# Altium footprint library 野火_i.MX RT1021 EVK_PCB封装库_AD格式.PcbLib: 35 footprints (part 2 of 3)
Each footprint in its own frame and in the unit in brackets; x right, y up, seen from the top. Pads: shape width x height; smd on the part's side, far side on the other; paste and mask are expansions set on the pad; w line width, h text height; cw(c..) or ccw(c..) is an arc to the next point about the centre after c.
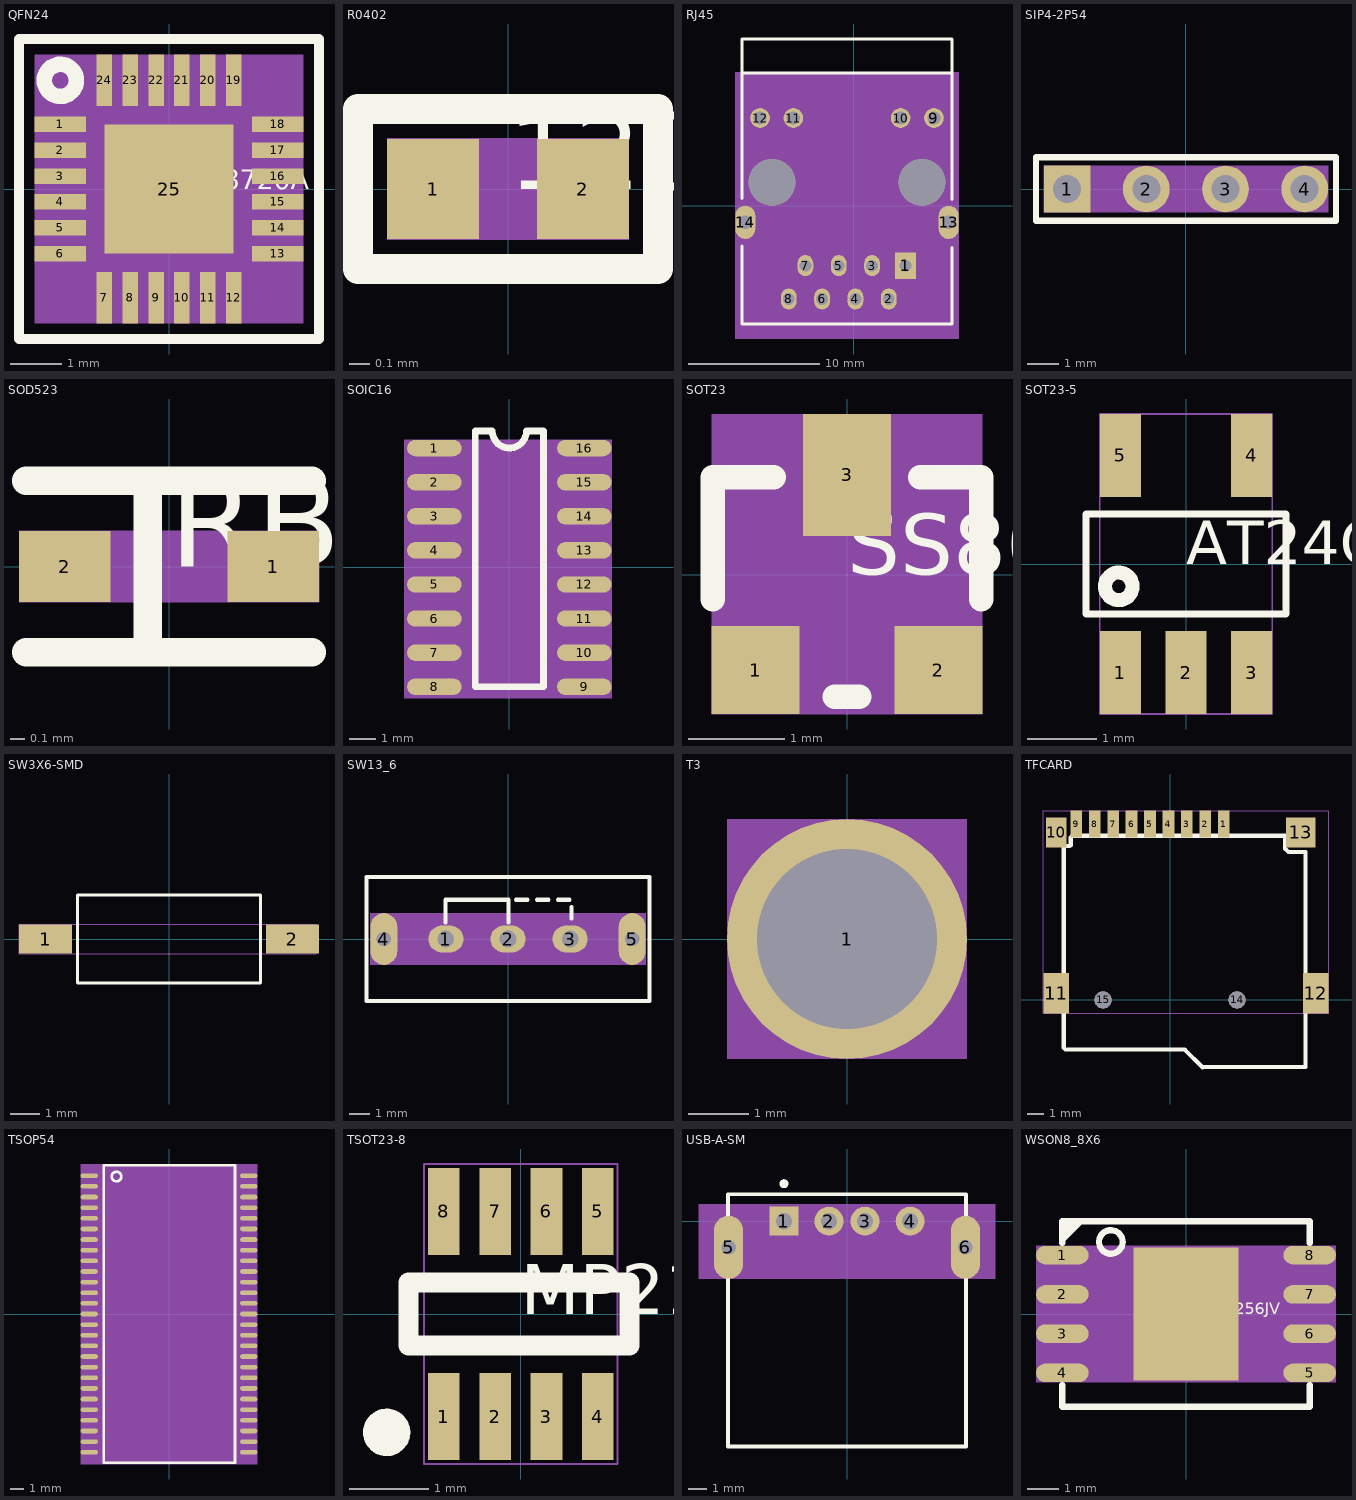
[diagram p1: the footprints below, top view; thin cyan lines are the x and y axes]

## QFN24 [mm] "QFN24"
pads (25):
  rect 1x0.3 smd: 1(-2.1,1.25) 2(-2.1,0.75) 3(-2.1,0.25) 4(-2.1,-0.25) 5(-2.1,-0.75) 6(-2.1,-1.25) 13(2.1,-1.25) 14(2.1,-0.75) 15(2.1,-0.25) 16(2.1,0.25) 17(2.1,0.75) 18(2.1,1.25)
  rect 0.3x1 smd: 7(-1.25,-2.1) 8(-0.75,-2.1) 9(-0.25,-2.1) 10(0.25,-2.1) 11(0.75,-2.1) 12(1.25,-2.1) 19(1.25,2.1) 20(0.75,2.1) 21(0.25,2.1) 22(-0.25,2.1) 23(-0.75,2.1) 24(-1.25,2.1)
  rect 2.5x2.5 smd: 25(0,0)
Top Overlay:
  circle w0.3: c-2.1,2.1 r0.31
  lines w0.2: -2.9,-2.9 -2.9,2.9 2.9,2.9 2.9,-2.9 -2.9,-2.9
  text "LAN8720A" at 0,0 h0.38
Mechanical 6:
  text "4" at -2.1,-0.098 h0.38
  text "19" at 1.25,2.405 h0.38
  text "1" at -2.1,1.402 h0.38
  text "14" at 2.1,-0.445 h0.38
  text "6" at -2.1,-1.098 h0.38
  text "24" at -1.25,2.405 h0.38
  text "15" at 2.1,0.055 h0.38
  text "25" at 0,0.305 h0.38
  text "21" at 0.25,2.405 h0.38
  text "20" at 0.75,2.405 h0.38
  text "2" at -2.1,0.902 h0.38
  text "23" at -0.75,2.405 h0.38
  text "22" at -0.25,2.405 h0.38
  text "3" at -2.1,0.402 h0.38
  text "5" at -2.1,-0.598 h0.38
  text "16" at 2.1,0.555 h0.38
  text "18" at 2.1,1.555 h0.38
  text "17" at 2.1,1.055 h0.38
  text "10" at 0.25,-1.795 h0.38
  text "7" at -1.25,-1.948 h0.38
  text "8" at -0.75,-1.948 h0.38
  text "12" at 1.25,-1.795 h0.38
  text "13" at 2.1,-0.945 h0.38
  text "11" at 0.75,-1.795 h0.38
  text "9" at -0.25,-1.948 h0.38
Mechanical 7:
  region: -2.6,-2.6 2.6,-2.6 2.6,2.6 -2.6,2.6
Mechanical 8:
  lines w0.2: -2.05,-2.05 -2.05,2.05 2.05,2.05 2.05,-2.05 -2.05,-2.05
3D body: height 3.81, standoff 0, extent -2.6,-2.6 2.6,2.6

## R0402 [mm] "R0402"
pads (2):
  rect 0.46x0.5 smd: 1(-0.375,0) 2(0.375,0)
Top Overlay:
  lines w0.15: -0.75,-0.4 -0.75,0.4 0.75,0.4 0.75,-0.4 -0.75,-0.4
  text "120 Ohm" at 0,0 h0.38
Mechanical 6:
  text "2" at 0.375,0.152 h0.38
  text "1" at -0.375,0.152 h0.38
Mechanical 7:
  region: -0.605,-0.255 0.605,-0.255 0.605,0.255 -0.605,0.255
3D body: height 3.81, standoff 0, extent -0.605,-0.255 0.605,0.255

## RJ45 [mil] "RJ45"
pads (16):
  rect 62.99x78.74 / inner round 60 / far side rect 62.99x78.74 hole 35.43: 1(155.2,-180)
  oval 47.24x62.99 / inner round 60 / far side oval 47.24x62.99 hole 35.43: 2(105.2,-280) 3(55.2,-180) 4(5.2,-280) 5(-44.8,-180) 6(-94.8,-280) 7(-144.8,-180) 8(-194.8,-280)
  round 59.06 / inner round 60 / far side round 59.06 hole 40.16: 9(240.83,262.91) 10(140.83,262.91) 11(-180.83,262.91) 12(-280.83,262.91)
  oval 60x100 / inner round 60 / far side oval 60x100 hole 40: 13(285.12,-50.08) 14(-325.12,-50.08)
  round 140 / inner round 60 / far side round 140 hole 140: " "(-245,70) " "(205,70)
Top Overlay:
  lines w7.87: -334.96,397.76 294.96,397.76
  lines w10: -334.96,-120.83 -334.96,-355 294.96,-355 294.96,-125.98 ; -334.96,22.64 -334.96,499.92 294.96,499.92 294.96,18.94
Mechanical 6:
  text "14" at -345.12,-50.08 h25
  text "13" at 265.12,-50.08 h25
  text "11" at -200.83,262.91 h25
  text "10" at 120.83,262.91 h25
  text "7" at -154.8,-180 h25
  text "8" at -204.8,-280 h25
  text "1" at 145.2,-180 h25
  text "2" at 95.2,-280 h25
  text "3" at 45.2,-180 h25
  text "6" at -104.8,-280 h25
  text "12" at -300.83,262.91 h25
  text "9" at 230.83,262.91 h25
  text "5" at -54.8,-180 h25
  text "4" at -4.8,-280 h25
Mechanical 7:
  region: -355.12,-400 315.12,-400 315.12,400 -355.12,400
3D body: height 150, standoff 0, extent -355.12,-400 315.12,400

## SIP4-2P54 [mil] "SIP4-2P54"
pads (4):
  rect 59.06x59.06 / inner round 60 / far side rect 59.06x59.06 hole 35.43: 1(-150,0)
  round 59.06 / inner round 60 / far side round 59.06 hole 35.43: 2(-50,0) 3(50,0) 4(150,0)
Top Overlay:
  lines w7.87: -189.37,-40 -189.37,40 189.57,40 189.57,-40 -189.37,-40
Mechanical 6:
  text "2" at -40,0 h25
  text "3" at 60,0 h25
  text "4" at 160,0 h25
  text "1" at -140,0 h25
Mechanical 7:
  region: -179.53,-29.53 179.53,-29.53 179.53,29.53 -179.53,29.53
3D body: height 150, standoff 0, extent -179.53,-29.53 179.53,29.53

## SOD523 [mm] "SOD523"
pads (2):
  rect 0.64x0.5 smd: 1(0.73,0) 2(-0.73,0)
Top Overlay:
  lines w0.2: -1,-0.6 1,-0.6 ; -1,0.6 1,0.6 ; -0.15,-0.575 -0.15,0.6
  text "RB521S30" at 0,0 h0.64
Mechanical 6:
  text "2" at -0.73,-0.254 h0.64
  text "1" at 0.73,-0.254 h0.64
Mechanical 7:
  region: -1.05,-0.25 1.05,-0.25 1.05,0.25 -1.05,0.25
3D body: height 3.81, standoff 0, extent -1.05,-0.25 1.05,0.25

## SOIC16 [mil] "SOIC16"
pads (16):
  oval 80x24 smd: 1(-110,175) 2(-110,125) 3(-110,75) 4(-110,25) 5(-110,-25) 6(-110,-75) 7(-110,-125) 8(-110,-175) 9(110,-175) 10(110,-125) 11(110,-75) 12(110,-25) 13(110,25) 14(110,75) 15(110,125) 16(110,175)
Top Overlay:
  lines w10: -50,-175 -50,200 -25,200 ccw(c0,200) 25,200 50,200 50,-175 -50,-175
Mechanical 6:
  text "3" at -110,65 h25
  text "16" at 110,155 h25
  text "7" at -110,-135 h25
  text "8" at -110,-185 h25
  text "4" at -110,15 h25
  text "2" at -110,115 h25
  text "5" at -110,-35 h25
  text "6" at -110,-85 h25
  text "1" at -110,165 h25
  text "14" at 110,55 h25
  text "11" at 110,-95 h25
  text "15" at 110,105 h25
  text "13" at 110,5 h25
  text "10" at 110,-145 h25
  text "12" at 110,-45 h25
  text "9" at 110,-185 h25
Mechanical 7:
  region: -154,-192 150,-192 150,187 -154,187
3D body: height 150, standoff 0, extent -154,-192 150,187

## SOT23 [mil] "SOT23"
pads (3):
  rect 36x36 smd: 1(-37.5,-39) 2(37.5,-39)
  rect 36x50 smd: 3(0,41)
Top Overlay:
  lines w10: -55,-10 -55,40 -30,40 ; -5,-50 5,-50 ; 30,40 55,40 55,-10
  text "SS8050" at 0,0 h25
Mechanical 6:
  text "3" at 0,51 h25
  text "1" at -37.5,-29 h25
  text "2" at 37.5,-29 h25
Mechanical 7:
  region: -55.5,-57 55.5,-57 55.5,66 -55.5,66
3D body: height 150, standoff 0, extent -55.5,-57 55.5,66

## SOT23-5 [mil] "SOT23-5"
pads (5):
  rect 23.62x47.24 smd: 1(-37.4,-62.01) 2(0,-62.01) 3(37.4,-62.01) 4(37.4,62.01) 5(-37.4,62.01)
Top Overlay:
  circle w8: c-38.4,-12.79 r7.87
  lines w4: -57.09,-28.54 -57.09,18.7 -57.09,28.54 57.09,28.54 57.09,18.7 57.09,-28.54 -57.09,-28.54
  text "AT24C02C-STUM-T" at 0,0 h25
Mechanical 6:
  text "3" at 27.4,-62.01 h25
  text "1" at -47.4,-62.01 h25
  text "2" at -10,-62.01 h25
  text "5" at -47.4,62.01 h25
  text "4" at 27.4,62.01 h25
Mechanical 7:
  lines w1: -49.21,-85.63 49.21,-85.63 49.21,85.63 -49.21,85.63 -49.21,-85.63

## SW3X6-SMD [mil] "SW3X6-SMD"
pads (2):
  rect 70.87x39.37 smd: 1(-165,0) 2(165,0)
Top Overlay:
  lines w3.94: -122.05,-59.06 122.05,-59.06 122.05,59.06 -122.05,59.06 -122.05,-59.06
Mechanical 6:
  text "1" at -175,0 h25
  text "2" at 155,0 h25
Mechanical 7:
  lines w1: -200.43,-19.69 196.5,-19.69 196.5,19.68 -200.43,19.68 -200.43,-19.69

## SW13_6 [mm] "SW13_6"
pads (5):
  oval 1.7x1.3 / inner round 1.524 / far side oval 1.7x1.3 hole 0.8: 1(-3,0) 2(0,0) 3(3,0)
  oval 1.3x2.5 / inner round 1.524 / far side oval 1.3x2.5 hole 0.7: 4(-6,0) 5(6,0)
Top Overlay:
  lines w0.203: -3.023,0.8 -3.023,1.9 0.025,1.9 0.025,0.8 ; 0.381,1.9 0.94,1.9 ; 1.397,1.9 1.956,1.9 ; 2.413,1.9 2.972,1.9 ; 3.073,0.984 3.073,1.543 ; -6.833,-3 -6.833,3 6.833,3 6.833,-3 -6.833,-3
Mechanical 6:
  text "1" at -2.746,0 h0.64
  text "2" at 0.254,0 h0.64
  text "3" at 3.254,0 h0.64
  text "5" at 6.254,0 h0.64
  text "4" at -5.746,0 h0.64
Mechanical 7:
  region: -6.65,-1.25 6.65,-1.25 6.65,1.25 -6.65,1.25
3D body: height 3.81, standoff 0, extent -6.65,-1.25 6.65,1.25

## T3 [mm] "T3"
pads (1):
  round 4 / inner round 1.524 / far side round 4 hole 3: 1(0,0)
Top Solder:
  pour cut-out: 2.5,-2.243 2.5,2.5 2.246,2.5 -2.5,2.5 -2.5,-2.246 -2.5,-2.5 2.246,-2.5 2.5,-2.5
Bottom Solder:
  pour cut-out: -2.5,-2.5 2.5,-2.5 2.5,2.5 -2.5,2.5
Mechanical 6:
  text "1" at 0.254,0 h0.64
Mechanical 7:
  region: -2,-2 2,-2 2,2 -2,2
3D body: height 3.81, standoff 0, extent -2,-2 2,2

## TFCARD [mil] "TFCARD"
pads (15):
  rect 27.56x62.99 smd: 1(125.98,413.39) 2(82.67,413.39) 3(39.37,413.39) 4(-3.94,413.39) 5(-47.25,413.39) 6(-90.55,413.39) 7(-133.86,413.39) 8(-177.17,413.39) 9(-220.48,413.39)
  rect 47.24x70 smd: 10(-267.72,393.7)
  rect 60x95 smd: 11(-267.72,15.75) 12(342.52,15.75)
  rect 70x70 smd: 13(307.08,393.7)
  round 40 / inner round 60 / far side round 40 hole 40: 14(157.48,0) 15(-157.48,0)
Top Overlay:
  lines w10: -251.72,361.75 -249.72,359.75 -249.72,-112.25 -245.72,-116.25 34.28,-116.25 76.28,-158.25 318.28,-157.48 318.28,347.75 278.28,347.75 270.28,355.75 270.28,385.75 -229.72,385.75 -233.72,381.75 -233.72,363.75 -235.72,361.75 -251.72,361.75
Mechanical 6:
  text "4" at -13.94,413.39 h25
  text "9" at -230.48,413.39 h25
  text "14" at 137.48,0 h25
  text "15" at -177.48,0 h25
  text "2" at 72.67,413.39 h25
  text "1" at 115.98,413.39 h25
  text "8" at -187.17,413.39 h25
  text "7" at -143.86,413.39 h25
  text "3" at 29.37,413.39 h25
  text "5" at -57.25,413.39 h25
  text "6" at -100.55,413.39 h25
  text "11" at -287.72,15.75 h25
  text "12" at 322.52,15.75 h25
  text "10" at -287.72,393.7 h25
  text "13" at 287.08,393.7 h25
Mechanical 7:
  lines w1: -297.72,-31.75 372.52,-31.75 372.52,444.88 -297.72,444.88 -297.72,-31.75

## TSOP54 [mm] "TSOP54"
pads (54):
  oval 1.3x0.35 smd: 1(-6,10.4) 2(-6,9.6) 3(-6,8.8) 4(-6,8) 5(-6,7.2) 6(-6,6.4) 7(-6,5.6) 8(-6,4.8) 9(-6,4) 10(-6,3.2) 11(-6,2.4) 12(-6,1.6) 13(-6,0.8) 14(-6,0) 15(-6,-0.8) 16(-6,-1.6) 17(-6,-2.4) 18(-6,-3.2) 19(-6,-4) 20(-6,-4.8) 21(-6,-5.6) 22(-6,-6.4) 23(-6,-7.2) 24(-6,-8) 25(-6,-8.8) 26(-6,-9.6) 27(-6,-10.4) 28(6,-10.4) 29(6,-9.6) 30(6,-8.8) 31(6,-8) 32(6,-7.2) 33(6,-6.4) 34(6,-5.6) 35(6,-4.8) 36(6,-4) 37(6,-3.2) 38(6,-2.4) 39(6,-1.6) 40(6,-0.8) 41(6,0) 42(6,0.8) 43(6,1.6) 44(6,2.4) 45(6,3.2) 46(6,4) 47(6,4.8) 48(6,5.6) 49(6,6.4) 50(6,7.2) 51(6,8) 52(6,8.8) 53(6,9.6) 54(6,10.4)
Top Overlay:
  circle w0.2: c-3.95,10.34 r0.361
  lines w0.2: -4.9,-11.2 -4.9,11.2 ; -4.9,-11.2 4.96,-11.2 ; -4.9,-11.2 -4.9,11.2 ; -4.9,-11.2 4.96,-11.2 ; -4.9,11.2 4.96,11.2 ; -4.9,11.2 4.96,11.2 ; 4.96,-11.2 4.96,11.2 ; 4.96,-11.2 4.96,11.2
Mechanical 6:
  text "40" at 6,-0.292 h0.64
  text "38" at 6,-1.892 h0.64
  text "16" at -6,-1.092 h0.64
  text "18" at -6,-2.692 h0.64
  text "39" at 6,-1.092 h0.64
  text "15" at -6,-0.292 h0.64
  text "44" at 6,2.908 h0.64
  text "42" at 6,1.308 h0.64
  text "13" at -6,1.308 h0.64
  text "11" at -6,2.908 h0.64
  text "10" at -6,3.708 h0.64
  text "8" at -6,5.054 h0.64
  text "7" at -6,5.854 h0.64
  text "5" at -6,7.454 h0.64
  text "53" at 6,10.108 h0.64
  text "51" at 6,8.508 h0.64
  text "50" at 6,7.708 h0.64
  text "48" at 6,6.108 h0.64
  text "47" at 6,5.308 h0.64
  text "45" at 6,3.708 h0.64
  text "4" at -6,8.254 h0.64
  text "2" at -6,9.854 h0.64
  text "19" at -6,-3.492 h0.64
  text "37" at 6,-2.692 h0.64
  text "17" at -6,-1.892 h0.64
  text "21" at -6,-5.092 h0.64
  text "20" at -6,-4.292 h0.64
  text "34" at 6,-5.092 h0.64
  text "33" at 6,-5.892 h0.64
  text "32" at 6,-6.692 h0.64
  text "31" at 6,-7.492 h0.64
  text "30" at 6,-8.292 h0.64
  text "29" at 6,-9.092 h0.64
  text "26" at -6,-9.092 h0.64
  text "25" at -6,-8.292 h0.64
  text "36" at 6,-3.492 h0.64
  text "35" at 6,-4.292 h0.64
  text "22" at -6,-5.892 h0.64
  text "24" at -6,-7.492 h0.64
  text "23" at -6,-6.692 h0.64
  text "49" at 6,6.908 h0.64
  text "43" at 6,2.108 h0.64
  text "3" at -6,9.054 h0.64
  text "1" at -6,10.654 h0.64
  text "9" at -6,4.254 h0.64
  text "14" at -6,0.508 h0.64
  text "27" at -6,-9.892 h0.64
  text "52" at 6,9.308 h0.64
  text "12" at -6,2.108 h0.64
  text "6" at -6,6.654 h0.64
  text "28" at 6,-9.892 h0.64
  text "54" at 6,10.908 h0.64
  text "46" at 6,4.508 h0.64
  text "41" at 6,0.508 h0.64
Mechanical 7:
  region: -6.65,-11.286 6.65,-11.286 6.65,11.286 -6.65,11.286
3D body: height 3.81, standoff 0, extent -6.65,-11.286 6.65,11.286

## TSOT23-8 [mil] "TSOT23-8"
pads (8):
  rect 15.75x43.31 smd: 1(-38.39,-51.18) 2(-12.8,-51.18) 3(12.8,-51.18) 4(38.39,-51.18) 5(38.39,51.18) 6(12.8,51.18) 7(-12.8,51.18) 8(-38.39,51.18)
Top Overlay:
  circle w11.81: c-66.93,-59.06 r5.91
  lines w10: -56.1,-15.75 -56.1,15.75 54.13,15.75 54.13,-15.75 -56.1,-15.75
  text "MP2144GJ" at 0,0 h25
Mechanical 6:
  text "1" at -48.39,-51.18 h25
  text "2" at -22.8,-51.18 h25
  text "3" at 2.8,-51.18 h25
  text "7" at -22.8,51.18 h25
  text "8" at -48.39,51.18 h25
  text "6" at 2.8,51.18 h25
  text "4" at 28.39,-51.18 h25
  text "5" at 28.39,51.18 h25
Mechanical 7:
  lines w1: -48.26,-74.83 48.26,-74.83 48.26,74.83 -48.26,74.83 -48.26,-74.83

## USB-A-SM [mil] "USB-A-SM"
pads (6):
  rect 62.99x62.99 / inner round 60 / far side rect 62.99x62.99 hole 35.43: 1(-137.8,0)
  round 62.99 / inner round 60 / far side round 62.99 hole 35.43: 2(-39.37,0) 3(39.37,0) 4(137.8,0)
  oval 62.99x137.8 / inner round 60 / far side oval 62.99x137.8 hole 31.5: 5(-258.67,-57.09) 6(258.67,-57.09)
Top Overlay:
  circle w9.84: c-137.8,81.69 r4.92
  lines w7.87: -259.85,-118.11 -259.85,-492.13 259.85,-492.13 259.85,-118.11 ; -259.85,0 -259.85,59.06 259.85,59.06 259.85,0
Mechanical 6:
  text "1" at -127.8,0 h25
  text "6" at 268.67,-57.09 h25
  text "5" at -248.67,-57.09 h25
  text "3" at 49.37,0 h25
  text "2" at -29.37,0 h25
  text "4" at 147.8,0 h25
Mechanical 7:
  region: -323.63,-125.98 323.63,-125.98 323.63,37.4 -323.63,37.4
3D body: height 150, standoff 0, extent -323.63,-125.98 323.63,37.4

## WSON8_8X6 [mm] "WSON8_8X6"
pads (9):
  oval 1.7x0.6 smd: 1(-4,1.905) 2(-4,0.635) 3(-4,-0.635) 4(-4,-1.905) 5(4,-1.905) 6(4,-0.635) 7(4,0.635) 8(4,1.905)
  rect 3.4x4.3 smd: " "(0,0)
Top Overlay:
  circle w0.203: c-2.43,2.33 r0.381
  lines w0.2: -4,-2.3 -4,-3 4,-3 4,-2.3 ; -4,2.3 -4,3 4,3 4,2.3 ; -4,2.4 -3.4,3 ; -4,2.6 -3.6,3 ; -4,2.8 -3.8,3
  text "W25Q256JV" at 0,0 h0.38
Top Paste:
  pour cut-out: 0.3,1.3 1.3,1.3 1.3,0.2 0.3,0.2
  pour cut-out: 0.3,-0.2 1.3,-0.2 1.3,-1.3 0.3,-1.3
  pour cut-out: -1.3,-0.2 -0.3,-0.2 -0.3,-1.3 -1.3,-1.3
  pour cut-out: -1.3,1.3 -0.3,1.3 -0.3,0.2 -1.3,0.2
Mechanical 6:
  text "4" at -3.848,-1.905 h0.38
  text "1" at -3.848,1.905 h0.38
  text "7" at 4.152,0.635 h0.38
  text "3" at -3.848,-0.635 h0.38
  text "2" at -3.848,0.635 h0.38
  text "5" at 4.152,-1.905 h0.38
  text "6" at 4.152,-0.635 h0.38
  text "8" at 4.152,1.905 h0.38
Mechanical 7:
  region: -4.85,-2.205 4.85,-2.205 4.85,2.205 -4.85,2.205
3D body: height 3.81, standoff 0, extent -4.85,-2.205 4.85,2.205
